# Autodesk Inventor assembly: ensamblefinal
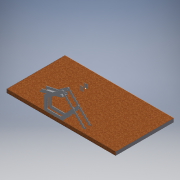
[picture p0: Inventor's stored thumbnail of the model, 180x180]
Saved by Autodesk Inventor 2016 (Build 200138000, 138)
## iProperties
Created: 2016-06
Part Number: ensamblefinal
Material: Genérico
Document SubType Name: Assembly
Designer: adm
Author: adm
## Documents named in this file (9)
- C:\Users\adm\Desktop\ensamblefinal.iam
- C:\Users\adm\Desktop\SOPORTE1.ipt
- C:\Users\adm\Desktop\soporte de rodillos(7.5mm).ipt
- C:\Users\adm\Desktop\soporte3s.ipt
- C:\Users\adm\Desktop\soporte2 de faja.ipt
- C:\Users\adm\Desktop\el ultimo\tablero.ipt
- C:\Users\adm\Desktop\rampa.ipt
- C:\Users\adm\Desktop\caja de motor de faja.ipt
- C:\Users\adm\Desktop\caja de motor de faja2.ipt
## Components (9 placed, 8 different names)
1. SOPORTE1:1
2. soporte de rodillos(7.5mm):2 — Coincidencia:2, Coincidencia:3, Nivelación:1, Nivelación:2
3. soporte3s:1 — Coincidencia:4, Nivelación:3, Coincidencia:7, Coincidencia:9, Coincidencia:10
4. soporte2 de faja:1 — Coincidencia:2, Coincidencia:3, Nivelación:3, Coincidencia:6, Nivelación:4, Nivelación:5, Coincidencia:8
5. soporte de rodillos(7.5mm):3 — Nivelación:1, Nivelación:2, Coincidencia:4
6. tablero:1 — Coincidencia:6, Nivelación:4
7. rampa:1 — Nivelación:5, Coincidencia:7, Coincidencia:8, Coincidencia:9, Coincidencia:10
8. caja de motor de faja:1
9. caja de motor de faja2:1
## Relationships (13: Mate 8, Flush 5)
- Coincidencia:2 [Mate]: soporte de rodillos(7.5mm):2 ↔ soporte2 de faja:1
- Coincidencia:3 [Mate]: soporte de rodillos(7.5mm):2 ↔ soporte2 de faja:1
- Nivelación:1 [Flush]: soporte de rodillos(7.5mm):2 ↔ soporte de rodillos(7.5mm):3
- Nivelación:2 [Flush]: soporte de rodillos(7.5mm):2 ↔ soporte de rodillos(7.5mm):3
- Coincidencia:4 [Mate]: soporte3s:1 ↔ soporte de rodillos(7.5mm):3
- Nivelación:3 [Flush]: soporte3s:1 ↔ soporte2 de faja:1
- Coincidencia:6 [Mate]: soporte2 de faja:1 ↔ tablero:1
- Nivelación:4 [Flush]: soporte2 de faja:1 ↔ tablero:1
- Nivelación:5 [Flush]: soporte2 de faja:1 ↔ rampa:1
- Coincidencia:7 [Mate]: soporte3s:1 ↔ rampa:1
- Coincidencia:8 [Mate]: soporte2 de faja:1 ↔ rampa:1
- Coincidencia:9 [Mate]: soporte3s:1 ↔ rampa:1
- Coincidencia:10 [Mate]: soporte3s:1 ↔ rampa:1
